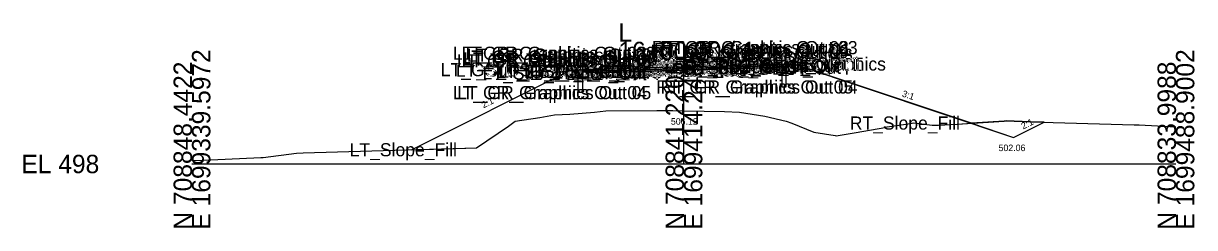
# Model space of a CAD drawing. Extents: x -63 to 1153, y -24 to 9522.
# Drawn here: x -25.7 to 152.8, y 7490.3 to 7521.4 of the extents above; entities that cross this region are included whole.
import ezdxf

# ---------------------------------------------------------------- set-up
doc = ezdxf.new("R2010")
doc.units = 0
for name, color, linetype in [('Default', 7, 'Continuous'), ('Exist Cross Section Cell', 7, 'Continuous'), ('Exist XS Center Line Elevation Label', 7, 'Continuous'), ('Exist XS Ground Line', 7, 'Continuous'), ('Prop CMT DNC', 7, 'Continuous'), ('Prop CMT Guardrail Graphics', 7, 'Continuous'), ('Prop CMT Pvmt Course 1', 7, 'Continuous'), ('Prop CMT Pvmt Course 2', 7, 'Continuous'), ('Prop CMT Pvmt Surface', 7, 'Continuous'), ('Prop CMT Pvmt Surface Overlay', 7, 'Continuous'), ('Prop CMT Pvmt Surface Shoulder', 7, 'Continuous'), ('Prop CMT Shld Paved Course 1', 7, 'Continuous'), ('Prop CMT Shld Paved Course 2', 7, 'Continuous'), ('Prop CMT Slope Grass', 7, 'Continuous'), ('Prop CMT Subgrade Earthwork', 7, 'Continuous'), ('Prop XS Ditch Standard Text', 7, 'Continuous'), ('Prop XS Earthwork Shape', 7, 'Continuous'), ('Prop XS EOT Tick Mark', 7, 'Continuous'), ('Prop XS SE Text', 7, 'Continuous'), ('Prop XS Side Slope Text', 7, 'Continuous')]:
    doc.layers.add(name, color=color, linetype=linetype)

msp = doc.modelspace()

# ---------------------------------------------------------------- linework, layer by layer
at = {"layer": 'Exist Cross Section Cell'}
for p, q in [((75, 7500), (75, 7518.63)), ((0, 7500), (75, 7500)), ((75, 7500), (150, 7500))]:
    msp.add_line(p, q, dxfattribs=at)
at = {"layer": 'Exist XS Ground Line'}
msp.add_lwpolyline([(0, 7500.56), (0.68, 7500.55), (10.51, 7500.98), (10.86, 7501.01), (15.96, 7501.64), (16.96, 7501.71), (32.66, 7502.14), (43.35, 7502.47), (48.27, 7505.74), (49.29, 7506.53), (53.05, 7507.07), (55.29, 7507.47), (57.61, 7507.59), (61.36, 7507.88), (63.09, 7508.1), (70.85, 7508.15), (73.3, 7508.15), (75, 7508.12), (81.17, 7508), (83.45, 7507.89), (87.31, 7507.3), (90.59, 7506.54), (91.46, 7506.2), (94.8, 7504.83), (98.07, 7504.32), (98.2, 7504.28), (101.23, 7504.78), (105.63, 7505.58), (106, 7505.66), (109.53, 7506.19), (110.05, 7506.27), (112.86, 7505.91), (113.82, 7505.94), (116.65, 7506.05), (123.81, 7506.55), (124.11, 7506.57), (127.78, 7506.44), (143.64, 7505.97), (143.94, 7505.97), (144.37, 7505.95), (150, 7505.64)], dxfattribs=at)
at = {"layer": 'Prop CMT Guardrail Graphics'}
for points in [[(58.86, 7510.88), (58.86, 7516.88)], [(58.86, 7516.88), (60.19, 7516.88), (60.46, 7516.59)], [(60.46, 7516.59), (60.19, 7516.3)], [(60.19, 7516.3), (60.46, 7516)], [(90.59, 7517.74), (89.26, 7517.74), (88.99, 7517.44)], [(88.99, 7517.44), (89.26, 7517.15)], [(89.26, 7517.15), (88.99, 7516.86)], [(88.99, 7516.86), (89.26, 7516.57), (89.93, 7516.57)], [(89.93, 7516.57), (89.93, 7511.74)], [(90.59, 7511.74), (90.59, 7517.74)], [(60.46, 7516), (60.19, 7515.71), (59.53, 7515.71)], [(59.53, 7515.71), (59.53, 7510.88)], [(59.53, 7510.88), (58.86, 7510.88)], [(89.93, 7511.74), (90.59, 7511.74)]]:
    msp.add_lwpolyline(points, dxfattribs=at)
at = {"layer": 'Prop CMT Pvmt Course 1'}
for points in [[(75, 7514.82), (65, 7514.52)], [(65, 7514.27), (75, 7514.57)], [(65, 7514.52), (65, 7514.27)], [(75, 7514.82), (85, 7515.12)], [(85, 7514.87), (75, 7514.57)], [(75, 7514.7), (75, 7514.82)], [(75, 7514.7), (75, 7514.82)], [(75, 7514.57), (75, 7514.7), (75, 7514.7)], [(75, 7514.57), (75, 7514.7), (75, 7514.7)], [(85, 7515.12), (85, 7514.87)]]:
    msp.add_lwpolyline(points, dxfattribs=at)
at = {"layer": 'Prop CMT Pvmt Course 2'}
for points in [[(75, 7514.57), (65, 7514.27)], [(75, 7514.57), (85, 7514.87)], [(85, 7514.62), (75, 7514.32)], [(75, 7514.32), (75, 7514.57)], [(75, 7514.32), (75, 7514.57)], [(85, 7514.87), (85, 7514.62)], [(65, 7514.02), (75, 7514.32)], [(65, 7514.27), (65, 7514.02)]]:
    msp.add_lwpolyline(points, dxfattribs=at)
at = {"layer": 'Prop CMT Pvmt Surface'}
for points in [[(75, 7514.82), (65, 7514.52)], [(75, 7514.82), (85, 7515.12)]]:
    msp.add_lwpolyline(points, dxfattribs=at)
at = {"layer": 'Prop CMT Pvmt Surface Overlay'}
for points in [[(75, 7514.82), (65, 7514.52)], [(75, 7514.82), (85, 7515.12)]]:
    msp.add_lwpolyline(points, dxfattribs=at)
at = {"layer": 'Prop CMT Pvmt Surface Shoulder'}
for points in [[(65, 7514.52), (60.62, 7514.39)], [(85, 7515.12), (88.89, 7515.24)]]:
    msp.add_lwpolyline(points, dxfattribs=at)
at = {"layer": 'Prop CMT Shld Paved Course 1'}
for points in [[(65, 7514.52), (60.62, 7514.39), (60.37, 7514.13)], [(65, 7514.27), (65, 7514.52)], [(85, 7515.12), (88.89, 7515.24), (89.13, 7515)], [(85, 7514.87), (85, 7515.12)], [(89.13, 7515), (85, 7514.87)], [(60.37, 7514.13), (65, 7514.27)]]:
    msp.add_lwpolyline(points, dxfattribs=at)
at = {"layer": 'Prop CMT Shld Paved Course 2'}
for points in [[(85, 7514.87), (89.13, 7515)], [(85, 7514.62), (85, 7514.87)], [(89.38, 7514.75), (85, 7514.62)], [(89.13, 7515), (89.13, 7515)], [(89.13, 7515), (89.38, 7514.75)], [(60.37, 7514.13), (60.11, 7513.88)], [(60.11, 7513.88), (65, 7514.02)], [(65, 7514.27), (60.37, 7514.13)], [(60.37, 7514.13), (60.37, 7514.13)], [(65, 7514.02), (65, 7514.27)]]:
    msp.add_lwpolyline(points, dxfattribs=at)
at = {"layer": 'Prop CMT Slope Grass'}
for p, q in [((91.99, 7515.15), (125.25, 7504.06)), ((125.25, 7504.06), (129.89, 7506.38))]:
    msp.add_line(p, q, dxfattribs=at)
for points in [[(88.89, 7515.24), (88.99, 7515.24)], [(88.99, 7515.24), (91.99, 7515.15)], [(57.46, 7514.14), (33.52, 7502.17)], [(60.46, 7514.38), (57.46, 7514.14)], [(60.62, 7514.39), (60.46, 7514.38)]]:
    msp.add_lwpolyline(points, dxfattribs=at)
at = {"layer": 'Prop CMT Subgrade Earthwork'}
for points in [[(75, 7514.32), (85, 7514.62)], [(85, 7514.62), (89.38, 7514.75)], [(89.38, 7514.75), (89.83, 7515.21)], [(60.11, 7513.88), (59.67, 7514.31)], [(65, 7514.02), (60.11, 7513.88)], [(75, 7514.32), (65, 7514.02)]]:
    msp.add_lwpolyline(points, dxfattribs=at)
at = {"layer": 'Prop XS Earthwork Shape'}
for points in [[(91.46, 7506.2), (94.8, 7504.83), (98.07, 7504.32), (98.2, 7504.28), (101.23, 7504.78), (105.63, 7505.58), (106, 7505.66), (109.53, 7506.19), (110.05, 7506.27), (112.86, 7505.91), (113.82, 7505.94), (116.65, 7506.05), (118.83, 7506.2), (91.99, 7515.15), (89.83, 7515.21), (89.38, 7514.75), (85, 7514.62), (75, 7514.32), (65, 7514.02), (60.11, 7513.88), (59.67, 7514.31), (57.46, 7514.14), (33.52, 7502.17), (43.35, 7502.47), (48.27, 7505.74), (49.29, 7506.53), (53.05, 7507.07), (55.29, 7507.47), (57.61, 7507.59), (61.36, 7507.88), (63.09, 7508.1), (70.85, 7508.15), (73.3, 7508.15), (75, 7508.12), (81.17, 7508), (83.45, 7507.89), (87.31, 7507.3), (90.59, 7506.54)], [(125.25, 7504.06), (129.89, 7506.38), (127.78, 7506.44), (124.11, 7506.57), (123.81, 7506.55), (118.83, 7506.2)]]:
    msp.add_lwpolyline(points, close=True, dxfattribs=at)
at = {"layer": 'Prop XS EOT Tick Mark'}
for points in [[(65, 7514.52), (65, 7515.52)], [(85, 7515.12), (85, 7516.12)]]:
    msp.add_lwpolyline(points, dxfattribs=at)

# ---------------------------------------------------------------- texts
at = {"layer": 'Default'}
msp.add_text('-', height=0.0001, dxfattribs=at).set_placement((0, 7500))
at = {"layer": 'Exist Cross Section Cell'}
for s, p in [('L', (65, 7518.63)), ('16+00.00 / 1', (65, 7515.83)), ('EL 498', (-26, 7498.6))]:
    msp.add_text(s, height=2.8, dxfattribs=at).set_placement(p)
for s, p in [('E 1699339.5972', (2.8, 7490)), ('E 1699414.2487', (77.8, 7490)), ('E 1699488.9002', (152.8, 7490)), ('N 708848.4422', (0, 7490)), ('N 708841.2205', (75, 7490)), ('N 708833.9988', (150, 7490))]:
    msp.add_text(s, height=2.8, rotation=90, dxfattribs=at).set_placement(p)
at = {"layer": 'Exist XS Center Line Elevation Label'}
msp.add_text('506.12', height=1, dxfattribs=at).set_placement((73.01, 7505.99))
at = {"layer": 'Prop CMT DNC'}
for s, p in [('RT_GR_Graphics Out 02', (70.11, 7516.74)), ('RT_GR_Graphics Out 09', (70.11, 7516.15)), ('RT_GR_Graphics Out 01', (70.41, 7516.44)), ('RT_GR_Graphics Out 03', (71.45, 7516.74)), ('LT_GR_Graphics Out 03', (39.76, 7515.88)), ('LT_GR_Graphics Out 06', (40.38, 7514.71)), ('LT_GR_Graphics Out 02', (41.09, 7515.88)), ('LT_GR_Graphics Out 09', (41.09, 7515.3)), ('LT_GR_Graphics Out 07', (41.09, 7514.71)), ('LT_GR_Graphics Out 08', (41.36, 7515)), ('LT_GR_Graphics Out 01', (41.93, 7515.59)), ('LT_TM_OEOT', (55.94, 7514.52)), ('RT_GS_OS_GR_Face_Graphics', (66.4, 7514.24)), ('RT_GR_Graphics Out 08', (69.84, 7515.86)), ('RT_GR_Graphics Out 07', (70.11, 7515.57)), ('RT_Sub_Trench_Out_DLT', (70.35, 7514.21)), ('RT_GR_Graphics Out 06', (70.73, 7515.57)), ('RT_TM_OEOT', (75.9, 7515.12)), ('RT_PS1_OEOP', (79.65, 7514.24)), ('LT_GS_OS_GR_Face_Graphics', (37.92, 7513.38)), ('LT_Sub_Trench_Out_DLT', (40.24, 7513.31)), ('LT_Sub_Trench_Out', (44.31, 7512.88)), ('LT_PS2_Shelf_Out', (46.35, 7513.13)), ('LT_GS_OS_CTL', (46.84, 7513.14)), ('LT_PS2_OEOP', (50.6, 7513.13)), ('LT_PS1_OEOP', (51.43, 7513.39)), ('LT_Sub_OEOT', (55.08, 7513.02)), ('LT_PV2_OEOT', (55.17, 7513.27)), ('LT_PV1_OEOT', (55.74, 7513.52)), ('RT_PV1_OEEOP_W', (62.94, 7513.7)), ('LT_PV1_OEEOP_W', (62.98, 7513.7)), ('RT_Sub_OEEOP', (64.17, 7513.32)), ('LT_Sub_OEEOP', (64.21, 7513.32)), ('RT_PV2_OEEOP', (64.26, 7513.57)), ('LT_PV2_OEEOP', (64.31, 7513.57)), ('PV1_PGL_W', (67.58, 7513.7)), ('PV1_PGL', (69.47, 7513.82)), ('RT_Sub_Trench_Out', (73.53, 7513.75)), ('RT_Sub_OEOT', (75.03, 7513.62)), ('RT_PS2_Shelf_Out', (75.07, 7514)), ('RT_PV2_OEOT', (75.13, 7513.87)), ('RT_PV1_OEOT', (75.69, 7514.12)), ('RT_PS2_OEOP', (79.32, 7514)), ('RT_GS_OS_CTL', (81.31, 7514.15)), ('RT_GR_Graphics Out 05', (70.78, 7510.74)), ('RT_GR_Graphics Out 04', (71.45, 7510.74)), ('LT_GR_Graphics Out 04', (39.76, 7509.88)), ('LT_GR_Graphics Out 05', (40.43, 7509.88)), ('RT_Slope_Fill', (100.28, 7505.24)), ('LT_Slope_Fill', (24.04, 7501.17))]:
    msp.add_text(s, height=2, dxfattribs=at).set_placement(p)
at = {"layer": 'Prop XS Ditch Standard Text'}
msp.add_text('502.06', height=1, dxfattribs=at).set_placement((122.96, 7501.96))
at = {"layer": 'Prop XS SE Text'}
for p in [(68.22, 7515.62), (78.22, 7515.92)]:
    msp.add_text('0.030', height=1, rotation=1.7184, dxfattribs=at).set_placement(p)
at = {"layer": 'Prop XS Side Slope Text'}
for s, rotation, p in [('3:1', 341.5651, (108.16, 7510.31)), ('2:1', 26.5651, (44.45, 7508.47)), ('2:1', 26.5651, (126.72, 7505.25))]:
    msp.add_text(s, height=1, rotation=rotation, dxfattribs=at).set_placement(p)

doc.saveas('drawing.dxf')
